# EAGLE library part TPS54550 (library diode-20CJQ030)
Ti's TPS54550 4.5-V TO 20-V INPUT, 6-A OUTPUT SYNCHRONOUS PWM SWITCHER WITH INTEGRATED FET (SWIFT) Description: The TPS54550 is a medium output current synchronous buck PWM converter with an integrated high side MOSFET and a gate driver for an low side external MOSFET. Features include a high performance voltage error amplifier that enables maximum performance under transient conditions and flexibility in choosing the output filter inductors and capacitors. The TPS54550 has an under-voltage-lockout circuit to prevent start-up until the input voltage reaches 4.5V; a slow-start circuit to limit in-rush currents; and a power good output to indicate valid output conditions. The synchronization feature is configurable as either an input or an output for easy 180° out of phase synchronization. The TPS54550 device is available in a thermally enhanced 16-pin TSSOP (PWP) PowerPAD package. TI provides evaluation modules and the SWIFT? Designer software tool to aid in quickly achieving high-performance power supply designs to meet aggressive equipment development cycles. Features: 40 mW MOSFET Switch for High Efficiency at 6-A (7.5 Peak) Output Current Uses External Lowside MOSFET Output Voltage Adjustable Down to 0.891 V With 1% Accuracy Synchronizes to External Clock 180° Out of Phase Synchronization Wide PWM Frequency Fixed 250 kHz, 500 kHz or Adjustable 250 kHz to 700 kHz Adjustable Slow Start Adjustable Undervoltage Lockout Load Protected by Peak Current Limit and Thermal Shutdown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
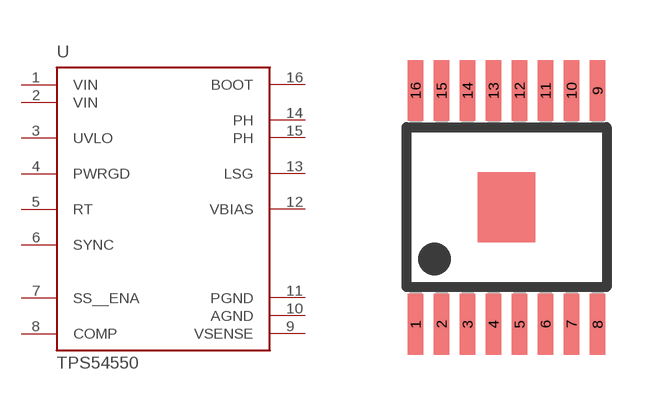
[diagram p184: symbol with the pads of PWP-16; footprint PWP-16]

Designator prefix U

## TPS54550  [PWP-16]
1  VIN  pwr
2  VIN  pwr
3  UVLO  in
4  PWRGD  out
5  RT  in
6  SYNC
7  SS__ENA  in
8  COMP  out
9  VSENSE  in
10  AGND  pwr
11  PGND  pwr
12  VBIAS  pas
13  LSG  out
14  PH  out
15  PH  out
16  BOOT  pas

## Footprint PWP-16 (pad centres in mm)
TI TPS54350 buck stepdown 3Amp switcher 16 pin TSSOP PowerPAD package (central pad is ground)
smd 0.381 x 1.524: 1 -2.275,-2.925; 2 -1.625,-2.925; 3 -0.975,-2.925; 4 -0.325,-2.925; 5 0.325,-2.925; 6 0.975,-2.925; 7 1.625,-2.925; 8 2.275,-2.925; 9 2.275,2.917; 10 1.625,2.917; 11 0.975,2.917; 12 0.325,2.917; 13 -0.325,2.917; 14 -0.975,2.917; 15 -1.625,2.917; 16 -2.275,2.917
